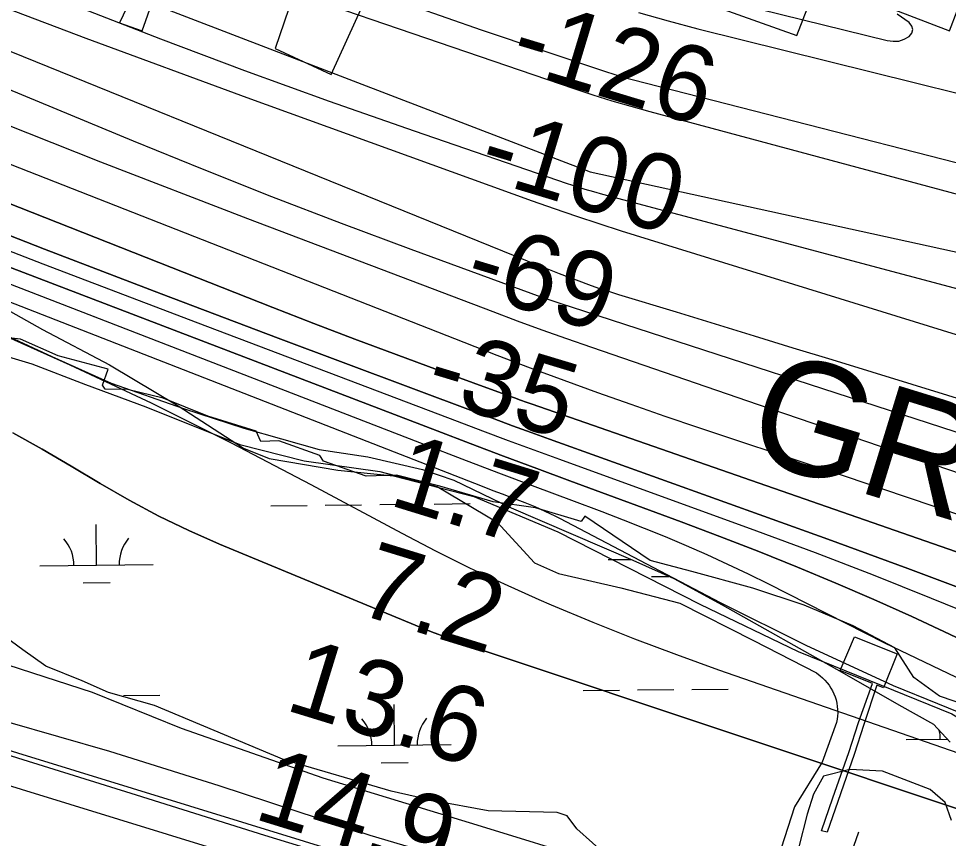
# Model space of a CAD drawing. Extents: x 3651524 to 3689615, y 505651 to 531377.
# Drawn here: x 3663457 to 3664278, y 513372 to 514096 of the extents above; entities that cross this region are included whole.
import ezdxf

# ---------------------------------------------------------------- set-up
doc = ezdxf.new("R2010")
doc.units = 0
for name, color, linetype in [('V-CHAN-DOCK', 7, 'Continuous'), ('V-FLOD-BASE', 7, 'Continuous'), ('V-LEVE-TOET', 7, 'Continuous'), ('V-RIVR-EDGE', 7, 'Continuous'), ('V-RIVR-RANG', 7, 'Continuous'), ('V-ROAD-CNTR', 7, 'Continuous'), ('V-RRAP-RVMT', 7, 'Continuous'), ('V-RRAP-RVMT-IDEN', 7, 'Continuous'), ('V-SITE-VEGE', 7, 'Continuous'), ('V-SURV-LINE', 7, 'Continuous'), ('V-TOPO-DPTH', 7, 'Continuous'), ('V-TOPO-MAJR', 7, 'Continuous'), ('V-TOPO-MINR', 7, 'Continuous'), ('V-TOPO-WATR', 7, 'Continuous'), ('V-WETL-SWMP', 7, 'Continuous')]:
    doc.layers.add(name, color=color, linetype=linetype)

msp = doc.modelspace()

# ---------------------------------------------------------------- linework, layer by layer
at = {"layer": 'V-CHAN-DOCK'}
msp.add_line((3664198.948, 513474.45), (3664211.226, 513509.039), dxfattribs=at)
for points in [[(3664211.226, 513509.039), (3664182.947, 513520.453), (3664195.6, 513550.165)], [(3664195.6, 513550.165), (3664233.086, 513535.075), (3664221.013, 513505.088), (3664215.15, 513507.456)], [(3664215.15, 513507.456), (3664203.638, 513472.679), (3664195.084, 513446.299), (3664171.46, 513377.639), (3664166.471, 513378.813)], [(3664166.471, 513378.813), (3664176.213, 513407.892), (3664190.392, 513448.07), (3664198.948, 513474.45)]]:
    msp.add_lwpolyline(points, dxfattribs=at)
at = {"layer": 'V-FLOD-BASE'}
msp.add_lwpolyline([(3663377.708, 513468.214), (3663456.221, 513443.315), (3663561.029, 513410.629), (3663674.533, 513375.09), (3663801.681, 513336.053), (3663905.503, 513304.52), (3664019.269, 513270.052), (3664125.947, 513237.196), (3664205.178, 513213.832)], dxfattribs=at)
at = {"layer": 'V-LEVE-TOET'}
msp.add_lwpolyline([(3663303.706, 513535.45), (3663343.867, 513518.269), (3663396.102, 513490.46), (3663447.388, 513475.114), (3663537.467, 513449.262), (3663634.247, 513418.989), (3663767.611, 513375.081), (3663940.64, 513323.789), (3664074.893, 513280.331), (3664160.984, 513250.006), (3664175.118, 513245.889)], dxfattribs=at)
at = {"layer": 'V-RIVR-EDGE'}
msp.add_lwpolyline([(3663391.419, 513870.496), (3663478.345, 513821.655), (3663537.7, 513790.291), (3663598.244, 513754.122), (3663655.783, 513716.759), (3663678.573, 513707.698), (3663739.18, 513697.343), (3663788.395, 513692.418), (3663859.188, 513674.233), (3663933.551, 513642.833), (3664058.861, 513578.888), (3664145.806, 513537.251), (3664281.343, 513482.286), (3664315.511, 513461.79), (3664385.697, 513440.605), (3664470.836, 513397.171), (3664515.808, 513376.048), (3664635.774, 513335.53), (3664695.736, 513307.166), (3664782.738, 513288.941), (3664815.709, 513269.649), (3664855.291, 513253.943), (3664905.707, 513249.016), (3665020.318, 513228.321)], dxfattribs=at)
at = {"layer": 'V-ROAD-CNTR'}
msp.add_lwpolyline([(3664200.376, 513222.786), (3664199.273, 513224.217), (3664177.97, 513257.093), (3664175.538, 513294.279), (3664180.27, 513323.259), (3664199.423, 513377.991)], dxfattribs=at)
at = {"layer": 'V-RRAP-RVMT'}
for points in [[(3663611.815, 514229.478), (3663546.509, 514092.425), (3663566.443, 514085.269), (3663619.754, 514236.068)], [(3663727.847, 514198.609), (3663683.776, 514069.778), (3663733.24, 514046.983), (3663808.811, 514212.31)], [(3664163.493, 514130.092), (3664279.35, 514085.276), (3664299.689, 514138.573), (3664429.623, 514088.186), (3664427.728, 514082.488), (3664529.637, 514042.751), (3664536.084, 514059.024), (3664667.871, 514008.118), (3664671.207, 514016.256), (3664816.949, 513959.334), (3664813.864, 513950.433), (3664930.737, 513904.879), (3664933.268, 513911.451), (3665064.256, 513860.311), (3665065.998, 513864.998), (3665197.777, 513813.471), (3665198.66, 513816.567), (3665329.859, 513765.036), (3665335.569, 513780.162), (3665481.171, 513722.981), (3665478.365, 513715.311), (3665609.408, 513663.482), (3665552.051, 513515.327), (3665787.533, 513447.498)], [(3664075.078, 514106.061), (3664144.558, 514081.389), (3664163.493, 514130.092)], [(3664307.56, 513485.076), (3664270.502, 513497.607), (3664247.938, 513514.124), (3664231.042, 513540.445), (3664194.233, 513559.743), (3664151.068, 513578.227), (3664105.697, 513592.998), (3664051.712, 513607.805), (3664015.15, 513617.654), (3663957.341, 513656.75), (3663954.038, 513652.163), (3663913.694, 513664.239), (3663876.462, 513669.262), (3663829.373, 513683.254), (3663790.93, 513692.832), (3663764.239, 513692.103), (3663726.686, 513705.444), (3663723.197, 513710.322), (3663687.26, 513723.233), (3663671.094, 513722.817), (3663667.161, 513731.693), (3663624.337, 513744.97), (3663584.992, 513760.857), (3663553.372, 513768.489), (3663533.818, 513768.993), (3663531.434, 513772.563), (3663536.377, 513786.561), (3663492.125, 513798.416), (3663458.943, 513812.962), (3663430.015, 513816.194)]]:
    msp.add_lwpolyline(points, dxfattribs=at)
at = {"layer": 'V-SITE-VEGE'}
for points in [[(3663436.443, 513801.147), (3663469.09, 513791.28), (3663516.456, 513773.041), (3663569.706, 513753.355), (3663652.704, 513720.077), (3663709.472, 513705.727), (3663776.411, 513696.198), (3663826.851, 513683.074), (3663880.064, 513651.379), (3663912.787, 513615.424), (3663934.097, 513606.223), (3663989.133, 513593.466), (3664041.371, 513580.027), (3664106.254, 513546.784), (3664161.773, 513518.257)], [(3663963.637, 513352.527), (3663866.038, 513382.634), (3663726.294, 513425.391), (3663601.166, 513469.101), (3663522.606, 513501.072), (3663416.127, 513535.569)], [(3664161.773, 513518.257), (3664165.062, 513515.722), (3664167.251, 513513.842), (3664169.308, 513511.814), (3664171.216, 513509.647), (3664172.971, 513507.356), (3664174.563, 513504.945), (3664175.984, 513502.432), (3664177.225, 513499.827), (3664178.284, 513497.142), (3664179.152, 513494.394), (3664179.828, 513491.592), (3664180.305, 513488.752), (3664180.584, 513485.888), (3664180.66, 513483.015), (3664180.535, 513480.146), (3664180.209, 513477.295), (3664179.687, 513474.477), (3664167.004, 513439.421), (3664142.382, 513399.881), (3664130.592, 513363.5)]]:
    msp.add_lwpolyline(points, dxfattribs=at)
at = {"layer": 'V-SURV-LINE'}
for points in [[(3663253.515, 513510.151), (3664371.349, 513165.761)], [(3664362.503, 513137.095), (3663244.669, 513481.485)]]:
    msp.add_lwpolyline(points, dxfattribs=at)
at = {"layer": 'V-TOPO-DPTH'}
for points in [[(3663056.546, 514087.907), (3663681.776, 513841.177), (3663718.04, 513827.03), (3663754.375, 513813.073), (3663790.819, 513799.401), (3663827.336, 513785.919), (3663890.243, 513762.973), (3663895.364, 513761.118), (3663900.49, 513759.279), (3663905.624, 513757.462), (3663910.763, 513755.66), (3664284.593, 513625.551), (3664400.185, 513584.495), (3664515.414, 513542.465), (3664630.099, 513498.975), (3664744.423, 513454.51), (3664944.386, 513375.27)], [(3664944.386, 513375.27), (3664744.423, 513454.51), (3664630.099, 513498.975), (3664515.414, 513542.465), (3664400.185, 513584.495), (3664284.593, 513625.551), (3663910.763, 513755.66), (3663905.624, 513757.462), (3663900.49, 513759.279), (3663895.364, 513761.118), (3663890.243, 513762.973), (3663827.336, 513785.919), (3663790.819, 513799.401), (3663754.375, 513813.073), (3663718.04, 513827.03), (3663681.776, 513841.177), (3663056.546, 514087.907)], [(3663273.31, 514036.731), (3663850.346, 513810.375), (3663879.742, 513798.992), (3663909.203, 513787.782), (3663938.761, 513776.83), (3663968.384, 513766.051), (3663998.095, 513755.517), (3664027.86, 513745.138), (3664057.704, 513734.99), (3664087.602, 513724.997), (3664134.09, 513709.66), (3664187.237, 513692.011), (3664240.337, 513674.224), (3664293.368, 513656.23), (3664346.351, 513638.099), (3664565.765, 513562.533), (3664661.933, 513529.111), (3664757.972, 513495.329), (3664853.82, 513461.007), (3664949.54, 513426.324)], [(3663273.31, 514036.731), (3663850.346, 513810.375), (3663879.742, 513798.992), (3663909.203, 513787.782), (3663938.761, 513776.83), (3663968.384, 513766.051), (3663998.095, 513755.517), (3664027.86, 513745.138), (3664057.704, 513734.99), (3664087.602, 513724.997), (3664134.09, 513709.66), (3664187.237, 513692.011), (3664240.337, 513674.224), (3664293.368, 513656.23), (3664346.351, 513638.099), (3664565.765, 513562.533), (3664661.933, 513529.111), (3664757.972, 513495.329), (3664853.82, 513461.007), (3664949.54, 513426.324)], [(3663023.668, 514012.226), (3663859.937, 513685.749), (3663868.053, 513682.596), (3663876.177, 513679.461), (3663884.311, 513676.354), (3663892.453, 513673.264), (3663899.7, 513670.528), (3663904.209, 513668.786), (3663908.697, 513666.996), (3663913.157, 513665.135), (3663917.598, 513663.227), (3663922.003, 513661.238), (3663926.378, 513659.189), (3663930.708, 513657.047), (3663935.01, 513654.844), (3664076.708, 513580.393), (3664152.595, 513542.669), (3664229.489, 513507.268), (3664307.894, 513475.352), (3664387.305, 513445.759), (3664986.642, 513237.611)], [(3663023.668, 514012.226), (3663859.937, 513685.749), (3663868.053, 513682.596), (3663876.177, 513679.461), (3663884.311, 513676.354), (3663892.453, 513673.264), (3663899.7, 513670.528), (3663904.209, 513668.786), (3663908.697, 513666.996), (3663913.157, 513665.135), (3663917.598, 513663.227), (3663922.003, 513661.238), (3663926.378, 513659.189), (3663930.708, 513657.047), (3663935.01, 513654.844), (3664076.708, 513580.393), (3664152.595, 513542.669), (3664229.489, 513507.268), (3664307.894, 513475.352), (3664387.305, 513445.759), (3664986.642, 513237.611)], [(3663377.159, 513932.872), (3663480.063, 513892.633), (3663583.235, 513853.085), (3663686.585, 513813.996), (3663861.096, 513748.659), (3663877.336, 513742.617), (3663893.592, 513736.619), (3663909.872, 513730.686), (3663926.169, 513724.798), (3664171.96, 513636.559), (3664242.703, 513610.63), (3664313.206, 513584.076), (3664383.349, 513556.587), (3664453.253, 513528.475), (3664506.968, 513506.456), (3664549.717, 513488.614), (3664592.31, 513470.413), (3664634.668, 513451.671), (3664676.87, 513432.569), (3664719.256, 513413.975), (3664762.046, 513396.414), (3664805.439, 513380.404), (3664849.235, 513365.427), (3665082.465, 513290.328)], [(3665082.465, 513290.328), (3664849.235, 513365.427), (3664805.439, 513380.404), (3664762.046, 513396.414), (3664719.256, 513413.975), (3664676.87, 513432.569), (3664634.668, 513451.671), (3664592.31, 513470.413), (3664549.717, 513488.614), (3664506.968, 513506.456), (3664453.253, 513528.475), (3664383.349, 513556.587), (3664313.206, 513584.076), (3664242.703, 513610.63), (3664171.96, 513636.559), (3663926.169, 513724.798), (3663909.872, 513730.686), (3663893.592, 513736.619), (3663877.336, 513742.617), (3663861.096, 513748.659), (3663686.585, 513813.996), (3663583.235, 513853.085), (3663480.063, 513892.633), (3663377.159, 513932.872)], [(3665044.545, 513268.754), (3664625.052, 513405.054), (3664560.076, 513427.707), (3664495.833, 513452.167), (3664432.689, 513479.339), (3664370.277, 513508.319), (3664312.531, 513536.642), (3664279.419, 513552.546), (3664246.139, 513568.083), (3664212.608, 513583.07), (3664178.909, 513597.69), (3664144.988, 513611.789), (3664110.937, 513625.562), (3664076.692, 513638.846), (3664042.318, 513651.804), (3663944.204, 513687.989), (3663914.813, 513698.89), (3663885.448, 513709.864), (3663856.124, 513720.947), (3663826.827, 513732.102), (3663437.515, 513881.159)], [(3665044.545, 513268.754), (3664625.052, 513405.054), (3664560.076, 513427.707), (3664495.833, 513452.167), (3664432.689, 513479.339), (3664370.277, 513508.319), (3664312.531, 513536.642), (3664279.419, 513552.546), (3664246.139, 513568.083), (3664212.608, 513583.07), (3664178.909, 513597.69), (3664144.988, 513611.789), (3664110.937, 513625.562), (3664076.692, 513638.846), (3664042.318, 513651.804), (3663944.204, 513687.989), (3663914.813, 513698.89), (3663885.448, 513709.864), (3663856.124, 513720.947), (3663826.827, 513732.102), (3663437.515, 513881.159)], [(3664932.276, 513182.957), (3664879.51, 513200.445), (3664826.762, 513217.985), (3664774.025, 513235.562), (3663865.772, 513538.789), (3663851.098, 513543.861), (3663836.499, 513549.137), (3663822.016, 513554.72), (3663807.608, 513560.508), (3663634.857, 513632.034), (3663607.744, 513644.009), (3663581.048, 513656.805), (3663554.979, 513670.834), (3663529.327, 513685.683), (3663503.867, 513700.937), (3663478.242, 513715.904), (3663452.372, 513730.441)]]:
    msp.add_lwpolyline(points, dxfattribs=at)
at = {"layer": 'V-TOPO-MAJR'}
for points in [[(3662936.854, 514354.926), (3663961.94, 513960.98), (3665180.012, 513694.091), (3665194.825, 513691.095), (3665209.689, 513688.419), (3665224.633, 513686.224), (3665239.628, 513684.349), (3665504.558, 513655.555), (3665522.521, 513655.947), (3665539.583, 513659.134), (3665555.292, 513666.513), (3665570.101, 513676.688), (3665582.267, 513687.621), (3665587.91, 513695.248), (3665591.356, 513703.342)], [(3663400.343, 514020.844), (3663529.639, 513969.782), (3663659.328, 513919.698), (3663875.973, 513837.442), (3663897.671, 513829.324), (3663919.42, 513821.346), (3663941.245, 513813.579), (3663963.121, 513805.952), (3664110.47, 513755.378), (3664206.086, 513722.653), (3664301.741, 513690.039), (3664397.452, 513657.591), (3664493.201, 513625.255), (3664829.509, 513512.002), (3664863.864, 513500.349), (3664898.186, 513488.597), (3664932.455, 513476.697)]]:
    msp.add_lwpolyline(points, dxfattribs=at)
at = {"layer": 'V-TOPO-MINR'}
for points in [[(3663578.724, 514160.815), (3663947.75, 514034.475), (3663964.367, 514028.972), (3663981.053, 514023.694), (3663997.842, 514018.753), (3664014.699, 514014.037), (3664692.199, 513831.835), (3664778.481, 513809.294), (3664864.966, 513787.583), (3664951.753, 513767.117)], [(3663170.75, 514149.296), (3663558.474, 513988.327), (3663619.422, 513963.479), (3663680.573, 513939.153), (3663742.03, 513915.609), (3663803.69, 513892.588), (3663909.655, 513853.794), (3663918.503, 513850.61), (3663927.374, 513847.492), (3663936.279, 513844.472), (3663945.206, 513841.517), (3664307.664, 513723.788), (3664449.71, 513677.757), (3664591.797, 513631.854), (3664733.947, 513586.144), (3664876.138, 513540.563), (3665097.328, 513469.823)], [(3663265.102, 514142.489), (3663917.295, 513877.922), (3663925.918, 513874.468), (3663934.561, 513871.066), (3663943.234, 513867.741), (3663951.927, 513864.467), (3663960.662, 513861.311), (3663969.433, 513858.261), (3663978.257, 513855.37), (3663987.118, 513852.585), (3664038.081, 513837.07), (3664072.444, 513826.59), (3664106.801, 513816.087), (3664141.147, 513805.55), (3664175.485, 513794.99), (3664795.985, 513603.826), (3664858.012, 513584.885), (3664920.101, 513566.151), (3664982.282, 513547.725)], [(3663375.213, 514132.803), (3663516.815, 514079.011), (3663658.908, 514026.489), (3663910.697, 513935.343), (3663930.303, 513928.4), (3663949.971, 513921.64), (3663969.731, 513915.156), (3663989.553, 513908.855), (3664219.735, 513837.448), (3664354.773, 513795.842), (3664489.917, 513754.585), (3664625.219, 513713.851), (3664760.627, 513673.465), (3665119.401, 513567.213), (3665150.614, 513558.1), (3665181.873, 513549.147), (3665213.2, 513540.436), (3665244.572, 513531.886), (3665478.629, 513469.062), (3665571.468, 513444.485), (3665664.417, 513420.335), (3665757.531, 513396.827)], [(3664036.611, 514123.397), (3664224.402, 514076.726), (3664229.535, 514076.152), (3664234.511, 514076.419), (3664239.255, 514077.949), (3664243.843, 514080.321), (3664246.105, 514083.424), (3664247.072, 514086.525)], [(3663508.313, 514107.065), (3663582.481, 514078.371), (3663656.899, 514050.355), (3663731.693, 514023.358), (3663806.737, 513997.039), (3663941.815, 513950.699), (3663949.533, 513948.141), (3663957.283, 513945.693), (3663965.084, 513943.408), (3663972.917, 513941.232), (3664916.492, 513689.752), (3664963.374, 513677.814), (3665010.415, 513666.576), (3665057.695, 513656.387), (3665105.133, 513646.898), (3665112.173, 513645.571), (3665156.301, 513637.918), (3665200.548, 513631.125), (3665244.974, 513625.623), (3665289.519, 513620.982), (3665976.659, 513559.489)], [(3663805.01, 514107.383), (3663865.769, 514086.374), (3663976.464, 514049.106), (3663982.075, 514047.286), (3663987.711, 514045.549), (3663993.384, 514043.938), (3663999.082, 514042.41), (3664440.458, 513929.256), (3664507.305, 513913.109), (3664574.413, 513898.211), (3664641.909, 513885.19), (3664709.664, 513873.42), (3664810.349, 513857.372), (3664823.007, 513859.494), (3664832.64, 513864.629), (3664837.733, 513874.283), (3664839.801, 513886.95), (3664835.082, 513903.444), (3664828.188, 513918.634), (3664818.033, 513931.868), (3664805.703, 513943.797), (3664767.99, 513972.621), (3664740.725, 513993.154), (3664713.27, 514013.424)], [(3664004.81, 514101.679), (3664030.869, 514094.219), (3664057.086, 514087.281), (3664479.626, 513982.269), (3664491.172, 513980.976), (3664502.368, 513981.578), (3664513.039, 513985.021), (3664523.36, 513990.358), (3664528.511, 513997.377), (3664530.742, 514004.413), (3664528.593, 514011.475), (3664523.525, 514018.553), (3664501.079, 514034.616), (3664479.764, 514049.513), (3664458.236, 514064.087)], [(3664247.072, 514086.525), (3664246.096, 514089.623), (3664243.823, 514092.718), (3664233.085, 514100.161)], [(3663056.546, 514087.907), (3663681.776, 513841.177), (3663718.04, 513827.03), (3663754.375, 513813.073), (3663790.819, 513799.401), (3663827.336, 513785.919), (3663890.243, 513762.973), (3663895.364, 513761.118), (3663900.49, 513759.279), (3663905.624, 513757.462), (3663910.763, 513755.66), (3664284.593, 513625.551), (3664400.185, 513584.495), (3664515.414, 513542.465), (3664630.099, 513498.975), (3664744.423, 513454.51), (3664944.386, 513375.27)], [(3663273.31, 514036.731), (3663850.346, 513810.375), (3663879.742, 513798.992), (3663909.203, 513787.782), (3663938.761, 513776.83), (3663968.384, 513766.051), (3663998.095, 513755.517), (3664027.86, 513745.138), (3664057.704, 513734.99), (3664087.602, 513724.997), (3664134.09, 513709.66), (3664187.237, 513692.011), (3664240.337, 513674.224), (3664293.368, 513656.23), (3664346.351, 513638.099), (3664565.765, 513562.533), (3664661.933, 513529.111), (3664757.972, 513495.329), (3664853.82, 513461.007), (3664949.54, 513426.324)], [(3663230.897, 513946.328), (3663816.625, 513719.798), (3663848.779, 513707.427), (3663880.962, 513695.133), (3663913.188, 513682.951), (3663945.442, 513670.845), (3663972.427, 513660.772), (3663991.155, 513653.62), (3664009.808, 513646.283), (3664028.349, 513638.666), (3664046.816, 513630.864), (3664065.147, 513622.753), (3664083.372, 513614.416), (3664101.438, 513605.74), (3664119.398, 513596.839), (3664222.056, 513544.761), (3664291.922, 513511.22), (3664362.661, 513479.76), (3664434.707, 513451.424), (3664507.626, 513425.17), (3665017.572, 513254.073)], [(3663342.076, 513932.594), (3663478.707, 513879.691), (3663615.562, 513827.361), (3663844.542, 513740.631), (3663867.091, 513732.14), (3663889.662, 513723.708), (3663912.265, 513715.363), (3663934.89, 513707.077), (3664108.972, 513643.705), (3664160.611, 513624.504), (3664212.065, 513604.831), (3664263.244, 513584.452), (3664314.239, 513563.602), (3664364.933, 513542.033), (3664415.41, 513519.978), (3664465.563, 513497.194), (3664515.499, 513473.923), (3664521.733, 513470.963), (3664575.05, 513446.926), (3664628.935, 513424.321), (3664683.673, 513403.865), (3664738.978, 513384.841), (3665064.491, 513280.028)], [(3663377.159, 513932.872), (3663480.063, 513892.633), (3663583.235, 513853.085), (3663686.585, 513813.996), (3663861.096, 513748.659), (3663877.336, 513742.617), (3663893.592, 513736.619), (3663909.872, 513730.686), (3663926.169, 513724.798), (3664171.96, 513636.559), (3664242.703, 513610.63), (3664313.206, 513584.076), (3664383.349, 513556.587), (3664453.253, 513528.475), (3664506.968, 513506.456), (3664549.717, 513488.614), (3664592.31, 513470.413), (3664634.668, 513451.671), (3664676.87, 513432.569), (3664719.256, 513413.975), (3664762.046, 513396.414), (3664805.439, 513380.404), (3664849.235, 513365.427), (3665082.465, 513290.328)], [(3663437.515, 513881.159), (3663826.827, 513732.102), (3663856.124, 513720.947), (3663885.448, 513709.864), (3663914.813, 513698.89), (3663944.204, 513687.989), (3664042.318, 513651.804), (3664076.692, 513638.846), (3664110.937, 513625.562), (3664144.988, 513611.789), (3664178.909, 513597.69), (3664212.608, 513583.07), (3664246.139, 513568.083), (3664279.419, 513552.546), (3664312.531, 513536.642), (3664370.277, 513508.319), (3664432.689, 513479.339), (3664495.833, 513452.167), (3664560.076, 513427.707), (3664625.052, 513405.054), (3665044.545, 513268.754)], [(3663430.275, 513822.662), (3663502.591, 513790.363), (3663574.311, 513756.833), (3663645.138, 513721.456), (3663715.371, 513684.848), (3663795.816, 513641.581), (3663825.568, 513626.075), (3663855.575, 513611.093), (3663885.961, 513596.897), (3663916.6, 513583.226), (3663927.752, 513578.423), (3663964.314, 513563.147), (3664001.084, 513548.408), (3664038.167, 513534.474), (3664075.458, 513521.077), (3664967.585, 513211.505)], [(3663452.372, 513730.441), (3663478.242, 513715.904), (3663503.867, 513700.937), (3663529.327, 513685.683), (3663554.979, 513670.834), (3663581.048, 513656.805), (3663607.744, 513644.009), (3663634.857, 513632.034), (3663807.608, 513560.508), (3663822.016, 513554.72), (3663836.499, 513549.137), (3663851.098, 513543.861), (3663865.772, 513538.789), (3664774.025, 513235.562), (3664826.762, 513217.985), (3664879.51, 513200.445), (3664932.276, 513182.957)]]:
    msp.add_lwpolyline(points, dxfattribs=at)
at = {"layer": 'V-TOPO-WATR'}
msp.add_lwpolyline([(3663023.668, 514012.226), (3663859.937, 513685.749), (3663868.053, 513682.596), (3663876.177, 513679.461), (3663884.311, 513676.354), (3663892.453, 513673.264), (3663899.7, 513670.528), (3663904.209, 513668.786), (3663908.697, 513666.996), (3663913.157, 513665.135), (3663917.598, 513663.227), (3663922.003, 513661.238), (3663926.378, 513659.189), (3663930.708, 513657.047), (3663935.01, 513654.844), (3664076.708, 513580.393), (3664152.595, 513542.669), (3664229.489, 513507.268), (3664307.894, 513475.352), (3664387.305, 513445.759), (3664986.642, 513237.611)], dxfattribs=at)
at = {"layer": 'V-WETL-SWMP'}
for p, q in [((3663680.179, 513665.915), (3663712.177, 513666.259)), ((3663728.176, 513666.432), (3663760.174, 513666.776)), ((3663776.173, 513666.948), (3663808.172, 513667.293)), ((3663824.171, 513667.465), (3663856.169, 513667.809)), ((3663526.142, 513613.512), (3663525.755, 513649.51)), ((3663978.024, 513618.376), (3663997.924, 513618.59)), ((3663476.145, 513612.974), (3663576.139, 513614.05)), ((3664016.188, 513603.355), (3664031.563, 513603.52)), ((3663514.309, 513597.953), (3663538.307, 513598.211)), ((3663955.86, 513502.699), (3663987.858, 513503.043)), ((3664003.857, 513503.215), (3664035.855, 513503.56)), ((3664051.854, 513503.732), (3664083.852, 513504.076)), ((3663549.975, 513498.33), (3663581.973, 513498.674)), ((3663789.305, 513454.473), (3663788.918, 513490.471)), ((3664241.187, 513459.337), (3664277.431, 513459.727)), ((3663739.308, 513453.935), (3663839.302, 513455.011)), ((3663777.472, 513438.914), (3663801.47, 513439.172))]:
    msp.add_line(p, q, dxfattribs=at)
for points in [[(3663449.369, 513815.216), (3663486.812, 513797.738), (3663539.063, 513774.171), (3663602.804, 513751.89), (3663656.259, 513734.487), (3663722.858, 513715.503), (3663765.586, 513709.135), (3663814.085, 513697.867), (3663841.636, 513688.554), (3663892.249, 513664.158), (3663999.622, 513617.858), (3664035.828, 513601.606), (3664078.635, 513578.405), (3664184.428, 513518.961), (3664234.651, 513490.047), (3664265.113, 513472.947), (3664279.968, 513457.005)], [(3664104.181, 513308.004), (3664089.666, 513308.004), (3664079.506, 513309.455), (3664064.99, 513319.616), (3664046.121, 513329.777), (3664040.314, 513329.777), (3664018.542, 513335.583), (3663995.317, 513344.292), (3663977.899, 513355.904), (3663950.32, 513380.58), (3663941.611, 513392.192), (3663932.902, 513395.095), (3663871.938, 513396.547), (3663824.038, 513405.256), (3663786.298, 513413.965), (3663691.949, 513441.544), (3663577.279, 513489.444), (3663536.637, 513501.056), (3663513.412, 513511.217), (3663481.479, 513524.28), (3663461.157, 513538.796), (3663440.836, 513553.311)], [(3664281.267, 513387.837), (3664275.461, 513403.804), (3664262.397, 513415.416), (3664220.303, 513431.383), (3664191.273, 513432.835), (3664168.048, 513427.029), (3664159.339, 513411.062), (3664153.533, 513393.644), (3664146.276, 513364.613), (3664140.469, 513344.292), (3664127.406, 513321.067), (3664117.245, 513312.358), (3664104.181, 513308.004)]]:
    msp.add_lwpolyline(points, dxfattribs=at)
for centre, start, end in [((3663470.897, 513613.392), 359.844864, 41.388523), ((3663581.377, 513614.581), 139.844861, 181.38852), ((3663734.06, 513454.353), 359.844864, 41.388523), ((3663844.54, 513455.543), 139.844861, 181.38852), ((3664235.939, 513459.755), 359.844864, 12.375304)]:
    msp.add_arc(centre, 35.246, start, end, dxfattribs=at)

# ---------------------------------------------------------------- texts
at = {"layer": 'V-RIVR-RANG'}
for s, rotation, p in [('-126', 343.196917, (3663888.727, 514052.55)), ('-100', 343.196917, (3663860.844, 513956.509)), ('-69', 343.196917, (3663848.366, 513855.818)), ('-35', 343.196917, (3663813.918, 513761.761)), ('1.7', 342.918326, (3663782.97, 513667.081)), ('7.2', 342.918326, (3663753.825, 513571.423)), ('13.6', 342.918326, (3663691.145, 513486.069)), ('14.9', 342.918326, (3663663.513, 513389.945))]:
    msp.add_text(s, height=67, rotation=rotation, dxfattribs=at).set_placement(p)
at = {"layer": 'V-RRAP-RVMT-IDEN'}
msp.add_text('GREENVILLE', height=99.9998, rotation=342.905892, dxfattribs=at).set_placement((3664095.725, 513710.042))

doc.saveas('drawing.dxf')
